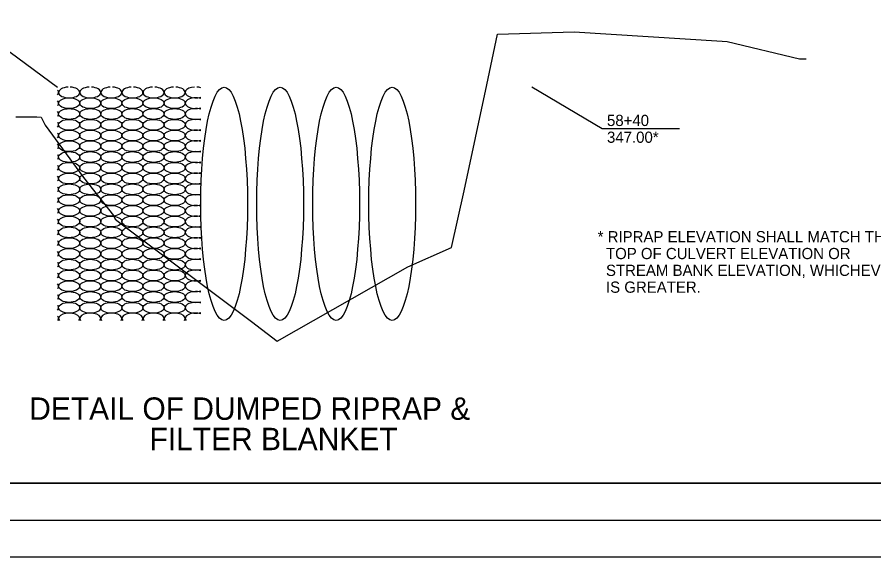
# Model space of a CAD drawing. Extents: x 3575 to 11445, y 9479 to 13278.
# Drawn here: x 6721.8 to 7180.7, y 10000 to 10288.9 of the extents above; entities that cross this region are included whole.
import ezdxf

# ---------------------------------------------------------------- set-up
doc = ezdxf.new("R2010")
doc.units = 0
for name, color, linetype in [('_Drafting 1', 7, 'Continuous'), ('Aggregate Base Course', 7, 'Continuous'), ('R_Culvert', 7, 'Continuous'), ('R_Dimension', 7, 'Continuous'), ('R_Exist Surface', 7, 'Continuous'), ('R_NoPlot', 7, 'Continuous'), ('STAMP_PE_CRAFTON-SIGNATURE', 7, 'Continuous'), ('STAMP_PRELIMINARY', 7, 'Continuous')]:
    doc.layers.add(name, color=color, linetype=linetype)

msp = doc.modelspace()

# ---------------------------------------------------------------- linework, layer by layer
at = {"layer": '_Drafting 1'}
msp.add_lwpolyline([(5884.86, 11066.7), (5884.86, 10039.4), (7465.76, 10039.4), (7465.76, 11002.7), (7250.26, 11002.7), (7250.26, 11001.26), (7234.07, 11001.26), (7234.07, 11017.3), (7054.46, 11017.3), (7054.46, 11066.7)], close=True, dxfattribs=at)
at = {"layer": 'Aggregate Base Course'}
for centre, start_param, end_param in [((6738.33, 10248.63), 2.699683, 3.583503), ((6749.63, 10248.63), 4.819748, 10.888219), ((6760.93, 10248.63), 4.819748, 10.888219), ((6772.23, 10248.63), 4.819748, 10.888219), ((6783.53, 10248.63), 4.819748, 10.888219), ((6794.83, 10248.63), 4.819748, 10.888219), ((6806.13, 10248.63), 4.819748, 10.888219), ((6817.43, 10248.63), 4.819748, 8.357955), ((6817.43, 10248.63), 4.208417, 4.605034), ((6738.33, 10242.87), 2.699683, 3.583503), ((6817.43, 10242.87), 4.208417, 8.357955), ((6817.43, 10237.11), 4.208417, 8.357955), ((6738.33, 10237.11), 2.699683, 3.583503), ((6817.43, 10231.34), 4.208417, 8.357955), ((6738.33, 10231.34), 2.699683, 3.583503), ((6738.33, 10225.58), 2.699683, 3.583503), ((6817.43, 10225.58), 4.208417, 8.357955), ((6738.33, 10219.82), 2.699683, 3.583503), ((6817.43, 10219.82), 4.208417, 8.357955), ((6817.43, 10214.05), 4.208417, 8.357955), ((6738.33, 10214.05), 2.699683, 3.583503), ((6738.33, 10208.29), 2.699683, 3.583503), ((6817.43, 10208.29), 4.208417, 8.357955), ((6738.33, 10202.53), 2.699683, 3.583503), ((6817.43, 10202.53), 4.208417, 8.357955), ((6738.33, 10196.76), 2.699683, 3.583503), ((6817.43, 10196.76), 4.208417, 8.357955), ((6817.43, 10191), 4.208417, 8.357955), ((6738.33, 10191), 2.699683, 3.583503), ((6738.33, 10185.24), 2.699683, 3.583503), ((6817.43, 10185.24), 4.208417, 8.357955), ((6738.33, 10179.48), 2.699683, 3.583503), ((6817.43, 10179.48), 4.208417, 8.357955), ((6738.33, 10173.71), 2.699683, 3.583503), ((6817.43, 10173.71), 4.208417, 8.357955), ((6817.43, 10167.95), 4.208417, 8.357955), ((6738.33, 10167.95), 2.699683, 3.583503), ((6738.33, 10162.19), 2.699683, 3.583503), ((6817.43, 10162.19), 4.208417, 8.357955), ((6738.33, 10156.42), 2.699683, 3.583503), ((6817.43, 10156.42), 4.208417, 8.357955), ((6817.43, 10150.66), 4.208417, 8.357955), ((6738.33, 10150.66), 2.699683, 3.583503), ((6817.43, 10144.9), 4.208417, 8.357955), ((6738.33, 10144.9), 2.699683, 3.583503), ((6738.33, 10139.13), 2.699683, 3.583503), ((6817.43, 10139.13), 4.208417, 8.357955), ((6738.33, 10133.37), 2.699683, 3.583503), ((6817.43, 10133.37), 4.208417, 8.357955), ((6749.63, 10127.61), 2.745366, 6.679416), ((6760.93, 10127.61), 2.745366, 6.679416), ((6772.23, 10127.61), 2.745366, 6.679416), ((6783.53, 10127.61), 2.745366, 6.679416), ((6794.83, 10127.61), 2.745366, 6.679416), ((6806.13, 10127.61), 2.745366, 6.679416), ((6817.43, 10127.61), 4.208417, 6.679416), ((6738.33, 10127.61), 2.745366, 3.583503)]:
    msp.add_ellipse(centre, major_axis=(-5.65, 0), ratio=0.51, start_param=start_param, end_param=end_param, dxfattribs=at)
for centre in [(6749.63, 10242.87), (6760.93, 10242.87), (6772.23, 10242.87), (6783.53, 10242.87), (6794.83, 10242.87), (6806.13, 10242.87), (6749.63, 10237.11), (6760.93, 10237.11), (6772.23, 10237.11), (6783.53, 10237.11), (6794.83, 10237.11), (6806.13, 10237.11), (6749.63, 10231.34), (6760.93, 10231.34), (6772.23, 10231.34), (6783.53, 10231.34), (6794.83, 10231.34), (6806.13, 10231.34), (6749.63, 10225.58), (6760.93, 10225.58), (6772.23, 10225.58), (6783.53, 10225.58), (6794.83, 10225.58), (6806.13, 10225.58), (6749.63, 10219.82), (6760.93, 10219.82), (6772.23, 10219.82), (6783.53, 10219.82), (6794.83, 10219.82), (6806.13, 10219.82), (6749.63, 10214.05), (6760.93, 10214.05), (6772.23, 10214.05), (6783.53, 10214.05), (6794.83, 10214.05), (6806.13, 10214.05), (6749.63, 10208.29), (6760.93, 10208.29), (6772.23, 10208.29), (6783.53, 10208.29), (6794.83, 10208.29), (6806.13, 10208.29), (6749.63, 10202.53), (6760.93, 10202.53), (6772.23, 10202.53), (6783.53, 10202.53), (6794.83, 10202.53), (6806.13, 10202.53), (6749.63, 10196.76), (6760.93, 10196.76), (6772.23, 10196.76), (6783.53, 10196.76), (6794.83, 10196.76), (6806.13, 10196.76), (6749.63, 10191), (6760.93, 10191), (6772.23, 10191), (6783.53, 10191), (6794.83, 10191), (6806.13, 10191), (6749.63, 10185.24), (6760.93, 10185.24), (6772.23, 10185.24), (6783.53, 10185.24), (6794.83, 10185.24), (6806.13, 10185.24), (6749.63, 10179.48), (6760.93, 10179.48), (6772.23, 10179.48), (6783.53, 10179.48), (6794.83, 10179.48), (6806.13, 10179.48), (6749.63, 10173.71), (6760.93, 10173.71), (6772.23, 10173.71), (6783.53, 10173.71), (6794.83, 10173.71), (6806.13, 10173.71), (6749.63, 10167.95), (6760.93, 10167.95), (6772.23, 10167.95), (6783.53, 10167.95), (6794.83, 10167.95), (6806.13, 10167.95), (6749.63, 10162.19), (6760.93, 10162.19), (6772.23, 10162.19), (6783.53, 10162.19), (6794.83, 10162.19), (6806.13, 10162.19), (6749.63, 10156.42), (6760.93, 10156.42), (6772.23, 10156.42), (6783.53, 10156.42), (6794.83, 10156.42), (6806.13, 10156.42), (6749.63, 10150.66), (6760.93, 10150.66), (6772.23, 10150.66), (6783.53, 10150.66), (6794.83, 10150.66), (6806.13, 10150.66), (6749.63, 10144.9), (6760.93, 10144.9), (6772.23, 10144.9), (6783.53, 10144.9), (6794.83, 10144.9), (6806.13, 10144.9), (6749.63, 10139.13), (6760.93, 10139.13), (6772.23, 10139.13), (6783.53, 10139.13), (6794.83, 10139.13), (6806.13, 10139.13), (6749.63, 10133.37), (6760.93, 10133.37), (6772.23, 10133.37), (6783.53, 10133.37), (6794.83, 10133.37), (6806.13, 10133.37)]:
    msp.add_ellipse(centre, major_axis=(-5.65, 0), ratio=0.51, dxfattribs=at)
at = {"layer": 'R_Culvert'}
for centre in [(6832.66, 10189), (6862.66, 10189), (6892.66, 10189), (6922.66, 10189)]:
    msp.add_ellipse(centre, major_axis=(0, 62.5), ratio=0.2, dxfattribs=at)
at = {"layer": 'R_Dimension'}
for points in [[(6675.07, 10270.2), (6717.94, 10270.2), (6743.44, 10251.5)], [(7076.64, 10229.15), (7035.24, 10229.15), (6997.44, 10251.5)]]:
    msp.add_lwpolyline(points, dxfattribs=at)
at = {"layer": 'R_Exist Surface'}
msp.add_lwpolyline([(6721.14, 10235.48), (6732.38, 10235.53), (6734.63, 10235.35), (6736.69, 10231.04), (6757.28, 10203.01), (6773.46, 10182.7), (6774.27, 10180.87), (6778.17, 10177.8), (6847.25, 10126), (6861.09, 10115.46), (6931.08, 10155.26), (6954.5, 10165.67), (6961.28, 10195.97), (6973.36, 10252.68), (6979.09, 10279.78), (7020.19, 10281.07), (7099.47, 10276.03), (7102.04, 10275.87), (7140.78, 10266.62), (7144.47, 10266.69)], dxfattribs=at)
at = {"layer": 'R_NoPlot'}
msp.add_lwpolyline([(5822.82, 11086.17), (7489.52, 11086.17), (7489.52, 10019.49), (5822.82, 10019.49)], close=True, dxfattribs=at)
at = {"layer": 'STAMP_PRELIMINARY'}
for p, q in [((7465.76, 10039.4), (5884.86, 10039.4)), ((5728.76, 10000), (7488.76, 10000))]:
    msp.add_line(p, q, dxfattribs=at)

# ---------------------------------------------------------------- texts
at = {"layer": 'R_Dimension'}
for s, p in [('58+40', (7037.74, 10230.65)), ('347.00*', (7037.74, 10221.65))]:
    msp.add_text(s, height=6, dxfattribs=at).set_placement(p)
at = {"layer": 'STAMP_PE_CRAFTON-SIGNATURE'}
for s, height, p in [('* RIPRAP ELEVATION SHALL MATCH THE ', 6, (7032.74, 10168.39)), ('  TOP OF CULVERT ELEVATION OR ', 6, (7032.74, 10159.39)), ('  STREAM BANK ELEVATION, WHICHEVER ', 6, (7032.74, 10150.39)), ('  IS GREATER.', 6, (7032.74, 10141.39)), ('DETAIL OF DUMPED RIPRAP &', 12, (6728.23, 10073.36)), ('FILTER BLANKET', 12, (6792.68, 10057.11))]:
    msp.add_text(s, height=height, dxfattribs=at).set_placement(p)

doc.saveas('drawing.dxf')
